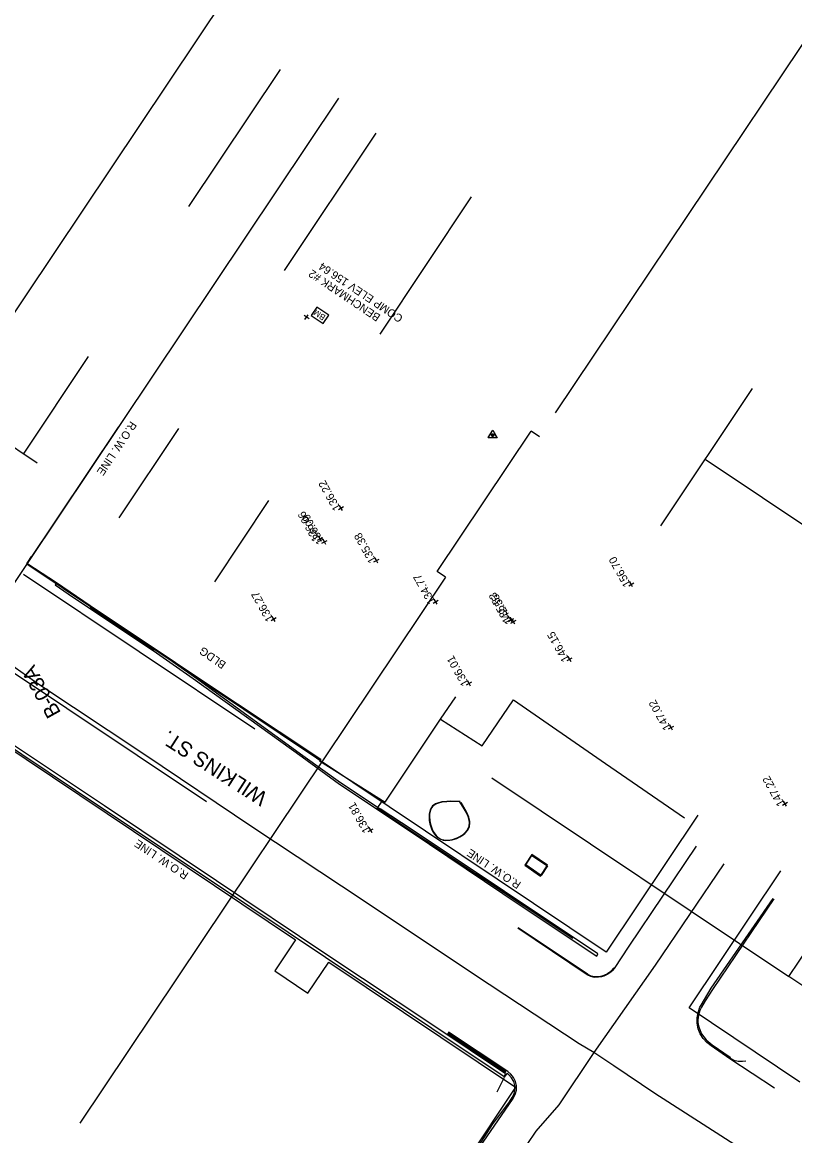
# Model space of a CAD drawing. Extents: x 13482447 to 13495412, y 324533 to 340229.
# Drawn here: x 13493376 to 13493623.3, y 331799.7 to 332156 of the extents above; entities that cross this region are included whole.
import ezdxf

# ---------------------------------------------------------------- set-up
doc = ezdxf.new("R2010")
doc.units = 0
for name, color, linetype in [('DETAIL_TEXT_DIMEN_PR', 7, 'Continuous'), ('V-ANNO-TEXT', 7, 'Continuous'), ('V-BLDG-IDEN', 7, 'Continuous'), ('V-BLDG-OTLN', 7, 'Continuous'), ('V-PROP-LINE', 7, 'Continuous'), ('V-PROP-RWAY', 7, 'Continuous'), ('V-PROP-RWAY-IDEN', 7, 'Continuous'), ('V-PVMT-BACK', 7, 'Continuous'), ('V-PVMT-CNTR', 7, 'Continuous'), ('V-PVMT-ROAD', 7, 'Continuous'), ('V-SITE-FENC-DEMO', 7, 'Continuous'), ('V-STRC-WALL', 7, 'Continuous'), ('V-SURV-DATA', 7, 'Continuous'), ('V-TOPO-DRAN-SPOT', 7, 'Continuous')]:
    doc.layers.add(name, color=color, linetype=linetype)

msp = doc.modelspace()

# ---------------------------------------------------------------- linework, layer by layer
at = {"layer": 'V-BLDG-OTLN'}
msp.add_lwpolyline([(13493378.89, 331985.09), (13493377.46, 331982.92), (13493386.97, 331976.78), (13493397.83, 331969.39), (13493418.9, 331955.32), (13493431.63, 331946.79), (13493471.68, 331920.24), (13493471.23, 331919.7), (13493492.17, 331906.46), (13493509.96, 331933.01), (13493514.85, 331940.2)], dxfattribs=at)
at = {"layer": 'V-PROP-LINE'}
for p, q in [((13493647.08, 332180.89), (13493546.7, 332030.99)), ((13493458.58, 332140.95), (13493429.28, 332097.03)), ((13493489.19, 332120.53), (13493459.89, 332076.6)), ((13493519.8, 332100.1), (13493490.5, 332056.18)), ((13493380.86, 332014.89), (13493298.26, 332070)), ((13493376.44, 332017.84), (13493397.28, 332049.07)), ((13493609.74, 332038.79), (13493580.37, 331994.92)), ((13493407.05, 331997.41), (13493426.13, 332026)), ((13493508.85, 331980.22), (13493538.93, 332025.13)), ((13493541.59, 332023.35), (13493538.93, 332025.13)), ((13493594.63, 332016.21), (13493689.69, 331952.57)), ((13493437.66, 331976.99), (13493454.98, 332002.94)), ((13493376.41, 331979.39), (13493450.52, 331929.95)), ((13493511.51, 331978.44), (13493508.85, 331980.22)), ((13493511.51, 331978.44), (13493394.51, 331803.72)), ((13493360.87, 331956.1), (13493434.98, 331906.65)), ((13493526.4, 331914.28), (13493621.46, 331850.64)), ((13493621.46, 331850.64), (13493639.84, 331878.1)), ((13493691.93, 331803.47), (13493621.46, 331850.64))]:
    msp.add_line(p, q, dxfattribs=at)
at = {"layer": 'V-PROP-RWAY'}
for p, q in [((13493198.41, 331801.59), (13493450.97, 332178.76)), ((13493477.23, 332131.7), (13493224.66, 331754.53)), ((13493377.46, 331982.61), (13493406.83, 332026.48)), ((13493562.93, 331858.44), (13493377.46, 331982.61)), ((13493368.47, 331926.05), (13493463.54, 331862.41)), ((13493592.3, 331902.32), (13493562.93, 331858.44)), ((13493589.52, 331840.64), (13493618.89, 331884.52)), ((13493463.54, 331862.41), (13493456.86, 331852.44)), ((13493467.5, 331845.32), (13493474.17, 331855.29)), ((13493474.17, 331855.29), (13493534, 331815.23)), ((13493456.86, 331852.44), (13493467.5, 331845.32)), ((13493625.01, 331816.89), (13493589.52, 331840.64)), ((13493534, 331815.23), (13493463.52, 331709.94))]:
    msp.add_line(p, q, dxfattribs=at)
at = {"layer": 'V-PVMT-BACK'}
for points in [[(13493616.68, 331875.54), (13493596.97, 331846.55), (13493594.7, 331842.93), (13493593.48, 331840.81), (13493593.01, 331839.8), (13493592.52, 331838.29), (13493592.32, 331836.76), (13493592.35, 331835.98), (13493592.52, 331834.92), (13493592.71, 331834.21), (13493593.26, 331832.86), (13493593.55, 331832.33), (13493594.21, 331831.34), (13493595, 331830.44), (13493595.6, 331829.88), (13493596.95, 331828.83), (13493602.65, 331824.85), (13493602.53, 331824.6)], [(13493507.69, 331774.06), (13493523.14, 331797.99), (13493526.58, 331803.26), (13493531.99, 331810.53), (13493532.93, 331811.94), (13493533.5, 331813.14), (13493533.78, 331814.45), (13493533.73, 331815.79), (13493533.37, 331817.08), (13493532.71, 331818.25), (13493531.8, 331819.23), (13493531.23, 331819.64)], [(13493528.12, 331813.75), (13493530.42, 331818.41), (13493531.23, 331819.64)]]:
    msp.add_lwpolyline(points, dxfattribs=at)
at = {"layer": 'V-PVMT-CNTR'}
for points in [[(13493605.37, 331796), (13493578.55, 331813.26), (13493565.46, 331822.12), (13493559.01, 331826.3), (13493554.28, 331829.11), (13493520.81, 331851.15), (13493485.5, 331874.76), (13493449.91, 331898.35), (13493414.95, 331921.85), (13493381.07, 331944.31), (13493362.78, 331957.08), (13493333.61, 331976.1), (13493307.04, 331993.94), (13493274.45, 332015.96), (13493240.12, 332038.89), (13493207.02, 332061.34), (13493179.15, 332079.98)], [(13493600.67, 331886.67), (13493578.69, 331854.34), (13493559.01, 331826.3), (13493547.8, 331809.65), (13493540.48, 331801.21), (13493517.42, 331767.01)]]:
    msp.add_lwpolyline(points, dxfattribs=at)
at = {"layer": 'V-PVMT-ROAD'}
for points in [[(13493418.72, 331955.35), (13493418.1, 331955.22), (13493398.02, 331968.53), (13493397.92, 331969.36)], [(13493509.96, 331933.01), (13493523.33, 331924.49), (13493533.35, 331939.16), (13493562.74, 331918.83), (13493588.08, 331901.39)], [(13493516.19, 331906.66), (13493513.28, 331906.72), (13493512.01, 331906.69), (13493510.34, 331906.52), (13493508.95, 331906.17), (13493508.37, 331905.92), (13493507.7, 331905.49), (13493507.41, 331905.23), (13493507.04, 331904.78), (13493506.63, 331903.97), (13493506.32, 331902.63), (13493506.28, 331901.97), (13493506.36, 331900.56), (13493506.55, 331899.48), (13493507.06, 331897.89), (13493507.42, 331897.15), (13493507.99, 331896.24), (13493508.32, 331895.83), (13493508.86, 331895.29), (13493509.78, 331894.67), (13493510.77, 331894.33), (13493511.48, 331894.21), (13493512.96, 331894.25), (13493513.72, 331894.39), (13493515.19, 331894.87), (13493516.12, 331895.31), (13493517.24, 331896.02), (13493517.73, 331896.42), (13493518.62, 331897.39), (13493519.05, 331898.16), (13493519.23, 331898.69), (13493519.35, 331899.82), (13493519.3, 331900.42), (13493518.98, 331901.7), (13493518.4, 331903.1), (13493517.88, 331904.12), (13493516.58, 331906.35)], [(13493516.04, 331906.59), (13493513.21, 331906.63), (13493511.98, 331906.58), (13493510.35, 331906.41), (13493509, 331906.06), (13493508.43, 331905.81), (13493507.78, 331905.39), (13493507.5, 331905.14), (13493507.15, 331904.7), (13493506.74, 331903.91), (13493506.45, 331902.57), (13493506.42, 331901.9), (13493506.51, 331900.49), (13493506.72, 331899.4), (13493507.26, 331897.82), (13493507.63, 331897.08), (13493508.22, 331896.18), (13493508.55, 331895.78), (13493509.11, 331895.25), (13493510.05, 331894.66), (13493511, 331894.36), (13493511.69, 331894.27), (13493513.11, 331894.35), (13493513.83, 331894.5), (13493515.24, 331894.99), (13493516.12, 331895.43), (13493517.18, 331896.14), (13493517.65, 331896.54), (13493518.49, 331897.48), (13493518.93, 331898.27), (13493519.1, 331898.82), (13493519.2, 331899.96), (13493519.13, 331900.57), (13493518.76, 331901.86), (13493518.12, 331903.27), (13493517.55, 331904.29), (13493516.12, 331906.54)], [(13493591.75, 331892.33), (13493570.21, 331860.4), (13493565.53, 331853.22), (13493564.94, 331852.47), (13493564.48, 331852.05), (13493563.46, 331851.36), (13493562.18, 331850.79), (13493561.51, 331850.58), (13493560.49, 331850.4), (13493559.39, 331850.38), (13493558.85, 331850.45), (13493558.05, 331850.66), (13493556.87, 331851.25), (13493534.68, 331866.09)], [(13493544.15, 331886.25), (13493539.23, 331889.67), (13493536.97, 331886.33), (13493541.99, 331882.75), (13493544.15, 331886.25)], [(13493542.13, 331883.02), (13493537.22, 331886.41), (13493539.21, 331889.41), (13493544.19, 331886.03), (13493542.13, 331883.02)], [(13493616.91, 331814.94), (13493602.55, 331824.35), (13493596.64, 331828.48), (13493595.24, 331829.54), (13493594.05, 331830.84), (13493593.12, 331832.33), (13493592.47, 331833.96), (13493592.13, 331835.69), (13493592.11, 331837.44), (13493592.41, 331839.17), (13493593.01, 331840.82), (13493593.35, 331841.47), (13493596.63, 331846.97), (13493616.4, 331875.64)], [(13493565.42, 331853.39), (13493564.59, 331852.44), (13493564.13, 331852.03), (13493563.36, 331851.52), (13493562.41, 331851.08), (13493561.91, 331850.9), (13493561.17, 331850.7), (13493560.29, 331850.54), (13493559.94, 331850.51), (13493559.21, 331850.53), (13493558.22, 331850.75), (13493557.72, 331850.94), (13493556.96, 331851.37), (13493534.76, 331866.21)], [(13493507.76, 331774.02), (13493523.6, 331797.69), (13493533.24, 331811.64), (13493533.88, 331812.9), (13493534.22, 331814.27), (13493534.24, 331815.69), (13493533.95, 331817.07), (13493533.35, 331818.35), (13493532.48, 331819.46), (13493531.47, 331820.3), (13493512.48, 331832.85)], [(13493530.9, 331819.95), (13493512.21, 331832.45)], [(13493530.9, 331819.95), (13493530.75, 331820.27), (13493512.38, 331832.71)], [(13493602.53, 331824.6), (13493603.82, 331823.94), (13493605.22, 331823.59), (13493606.66, 331823.54), (13493607.65, 331823.7)]]:
    msp.add_lwpolyline(points, dxfattribs=at)
at = {"layer": 'V-SITE-FENC-DEMO'}
msp.add_lwpolyline([(13493552.35, 331862.79), (13493489.68, 331904.46), (13493491.21, 331906.76)], dxfattribs=at)
at = {"layer": 'V-STRC-WALL'}
for points in [[(13493386.89, 331976.52), (13493386.54, 331975.99), (13493390.69, 331973.08), (13493397.85, 331968.32), (13493417.96, 331955.02), (13493430.8, 331946.06), (13493465.6, 331920.97), (13493477.6, 331912.25), (13493500.52, 331896.93), (13493535.78, 331873.23), (13493559.99, 331857.12), (13493560.36, 331857.87), (13493500.88, 331897.61), (13493490.65, 331904.27)], [(13493386.89, 331976.52), (13493391.13, 331973.7), (13493397.87, 331969.2), (13493397.95, 331968.48), (13493418.05, 331955.16), (13493418.65, 331955.29), (13493431.18, 331946.54), (13493465.91, 331921.42), (13493477.97, 331912.78), (13493490.65, 331904.27)], [(13493530.31, 331818.51), (13493530.79, 331819.47), (13493507.77, 331834.83), (13493473.6, 331857.65), (13493438.19, 331881.24), (13493402.32, 331905.28), (13493367.72, 331928.34), (13493351.29, 331939.37), (13493351.03, 331939.54)], [(13493530.31, 331818.51), (13493507.15, 331834.06), (13493473.12, 331856.78), (13493437.57, 331880.51), (13493401.84, 331904.3), (13493367.03, 331927.53), (13493352.79, 331937.07)]]:
    msp.add_lwpolyline(points, dxfattribs=at)
at = {"layer": 'V-SURV-DATA'}
for p, q in [((13493470.32, 332064.83), (13493468.54, 332062.17)), ((13493474.19, 332062.24), (13493470.32, 332064.83)), ((13493467.84, 332061.13), (13493466.25, 332062.2)), ((13493466.53, 332060.9), (13493467.56, 332062.44)), ((13493468.54, 332062.17), (13493472.41, 332059.58)), ((13493472.41, 332059.58), (13493474.19, 332062.24))]:
    msp.add_line(p, q, dxfattribs=at)
for points in [[(13493525.21, 332023.1), (13493526.65, 332025.52), (13493528.02, 332023.06)], [(13493525.22, 332023.09), (13493526.66, 332025.5), (13493528.03, 332023.04)], [(13493525.22, 332023.08), (13493526.66, 332025.5), (13493528.03, 332023.04)], [(13493525.23, 332023.09), (13493526.66, 332025.5), (13493528.04, 332023.04)], [(13493525.24, 332023.1), (13493526.68, 332025.51), (13493528.05, 332023.06)], [(13493525.24, 332023.07), (13493526.68, 332025.49), (13493528.05, 332023.03)], [(13493525.24, 332023.07), (13493526.68, 332025.49), (13493528.05, 332023.03)], [(13493525.24, 332023.07), (13493526.68, 332025.49), (13493528.05, 332023.03)], [(13493525.24, 332023.07), (13493526.68, 332025.49), (13493528.05, 332023.03)], [(13493525.24, 332023.07), (13493526.68, 332025.49), (13493528.05, 332023.03)], [(13493525.24, 332023.07), (13493526.68, 332025.49), (13493528.05, 332023.03)]]:
    msp.add_lwpolyline(points, close=True, dxfattribs=at)
for centre, radius in [((13493526.62, 332023.89), 0.406), ((13493526.64, 332023.87), 0.406), ((13493526.63, 332023.87), 0.406), ((13493526.64, 332023.87), 0.406), ((13493526.65, 332023.89), 0.406), ((13493526.65, 332023.86), 0.406), ((13493526.65, 332023.86), 0.406), ((13493526.65, 332023.86), 0.406), ((13493526.65, 332023.86), 0.406), ((13493526.65, 332023.86), 0.406), ((13493526.65, 332023.86), 0.406), ((13493526.62, 332023.89), 0.244), ((13493526.64, 332023.87), 0.244), ((13493526.64, 332023.87), 0.244), ((13493526.63, 332023.87), 0.244), ((13493526.65, 332023.89), 0.244), ((13493526.65, 332023.86), 0.244), ((13493526.65, 332023.86), 0.244), ((13493526.65, 332023.86), 0.244), ((13493526.65, 332023.86), 0.244), ((13493526.65, 332023.86), 0.244), ((13493526.65, 332023.86), 0.244), ((13493526.62, 332023.89), 0.0813), ((13493526.64, 332023.87), 0.0813), ((13493526.63, 332023.87), 0.0813), ((13493526.64, 332023.87), 0.0813), ((13493526.65, 332023.89), 0.0813), ((13493526.65, 332023.86), 0.0813), ((13493526.65, 332023.86), 0.0813), ((13493526.65, 332023.86), 0.0813), ((13493526.65, 332023.86), 0.0813), ((13493526.65, 332023.86), 0.0813), ((13493526.65, 332023.86), 0.0813)]:
    msp.add_circle(centre, radius, dxfattribs=at)
at = {"layer": 'V-TOPO-DRAN-SPOT'}
for p, q in [((13493477.24, 332000.12), (13493478.86, 332001.03)), ((13493478.52, 331999.74), (13493477.58, 332001.41)), ((13493470.61, 331990.24), (13493472.23, 331991.14)), ((13493471.89, 331989.85), (13493470.95, 331991.53)), ((13493471.99, 331989.29), (13493473.61, 331990.2)), ((13493473.27, 331988.91), (13493472.33, 331990.58)), ((13493488.63, 331983.33), (13493490.26, 331984.24)), ((13493489.91, 331982.95), (13493488.98, 331984.62)), ((13493570.19, 331975.72), (13493571.81, 331976.62)), ((13493571.46, 331975.33), (13493570.53, 331977.01)), ((13493507.59, 331970.17), (13493509.21, 331971.08)), ((13493508.86, 331969.78), (13493507.93, 331971.46)), ((13493455.72, 331964.61), (13493457.34, 331965.51)), ((13493457, 331964.22), (13493456.06, 331965.9)), ((13493531.75, 331964.26), (13493533.37, 331965.17)), ((13493533.02, 331963.88), (13493532.09, 331965.55)), ((13493532.49, 331963.75), (13493534.11, 331964.65)), ((13493533.77, 331963.36), (13493532.84, 331965.04)), ((13493550.46, 331951.73), (13493552.08, 331952.64)), ((13493551.74, 331951.35), (13493550.8, 331953.02)), ((13493518.31, 331944.01), (13493519.93, 331944.91)), ((13493519.58, 331943.62), (13493518.65, 331945.3)), ((13493582.98, 331929.87), (13493584.6, 331930.77)), ((13493584.26, 331929.48), (13493583.32, 331931.16)), ((13493619.4, 331905.53), (13493621.02, 331906.43)), ((13493620.68, 331905.14), (13493619.74, 331906.82)), ((13493486.74, 331897.03), (13493488.36, 331897.94)), ((13493488.02, 331896.65), (13493487.08, 331898.33))]:
    msp.add_line(p, q, dxfattribs=at)

# ---------------------------------------------------------------- texts
at = {"layer": 'DETAIL_TEXT_DIMEN_PR'}
msp.add_text('B-03A', height=4.8, rotation=119.1605, dxfattribs=at).set_placement((13493388.53, 331935.07))
at = {"layer": 'V-ANNO-TEXT'}
msp.add_text('WILKINS ST.', height=4.8, rotation=147.221, dxfattribs=at).set_placement((13493454.93, 331909.01))
at = {"layer": 'V-BLDG-IDEN'}
msp.add_text('BLDG', height=2.56, rotation=145.0433, dxfattribs=at).set_placement((13493441.5, 331951))
at = {"layer": 'V-PROP-RWAY-IDEN'}
for rotation, p in [(236.2892, (13493410.73, 332028.55)), (146.1996, (13493429.5, 331883.65)), (146.1996, (13493535.95, 331880.65))]:
    msp.add_text('R.O.W. LINE', height=2.56, rotation=rotation, dxfattribs=at).set_placement(p)
at = {"layer": 'V-SURV-DATA'}
for s, height, p in [('COMP ELEV 156.64', 2.56, (13493498.15, 332061.85)), ('BENCHMARK #2', 2.56, (13493490.94, 332062.22)), ('BM', 1.92, (13493473.3, 332062.06))]:
    msp.add_text(s, height=height, rotation=146.2011, dxfattribs=at).set_placement(p)
at = {"layer": 'V-TOPO-DRAN-SPOT'}
for s, p in [('136.22', (13493478.05, 332000.57)), ('136.06', (13493471.42, 331990.69)), ('136.09', (13493472.8, 331989.75)), ('135.38', (13493489.45, 331983.79)), ('156.70', (13493571, 331976.17)), ('134.77', (13493508.4, 331970.62)), ('136.27', (13493456.53, 331965.06)), ('135.53', (13493532.56, 331964.72)), ('142.55', (13493533.3, 331964.2)), ('146.15', (13493551.27, 331952.18)), ('136.01', (13493519.12, 331944.46)), ('147.02', (13493583.79, 331930.32)), ('147.22', (13493620.21, 331905.98)), ('136.81', (13493487.55, 331897.49))]:
    msp.add_text(s, height=2.56, rotation=119.1605, dxfattribs=at).set_placement(p)

doc.saveas('drawing.dxf')
